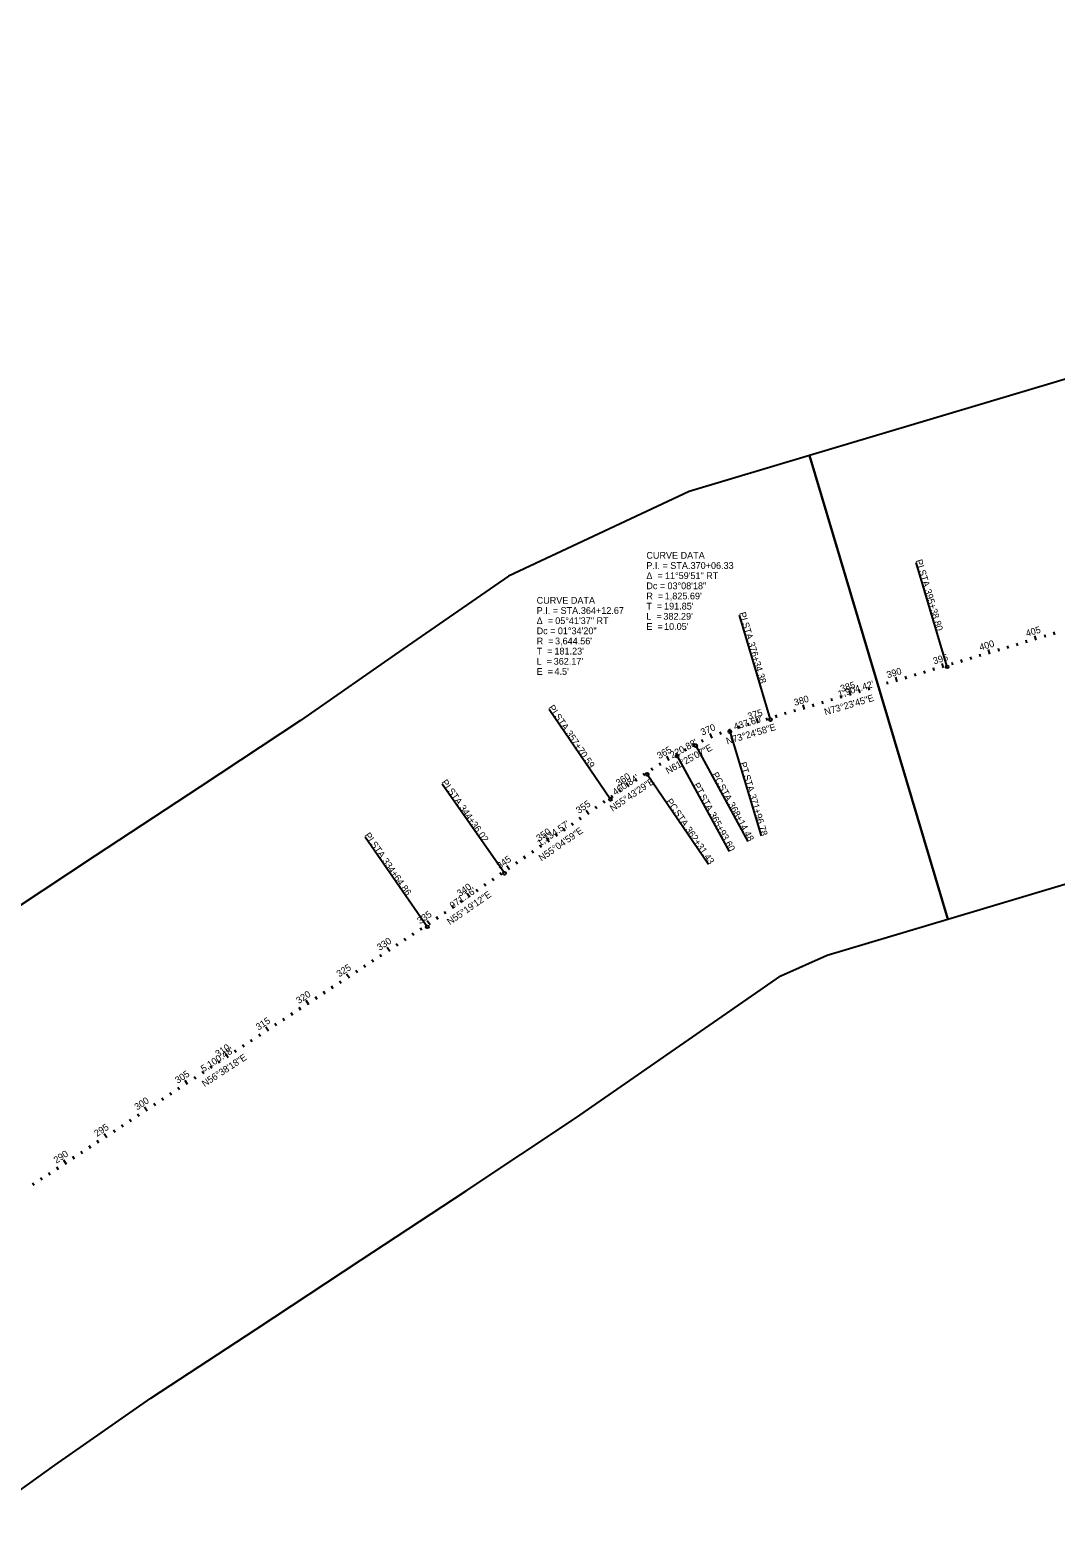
# Model space of a CAD drawing. Extents: x 187058 to 230449, y 263308 to 297406.
# Drawn here: x 208999 to 219600, y 281824 to 297406 of the extents above; entities that cross this region are included whole.
import ezdxf

# ---------------------------------------------------------------- set-up
doc = ezdxf.new("R2010")
doc.units = 0
for name, color, linetype in [('BR_X_Gen_Approach_Slab', 7, 'Continuous'), ('BR_X_SV_Deck_Top', 7, 'Continuous'), ('PV_X_Curb', 7, 'Continuous'), ('PV_X_Walk', 7, 'Continuous'), ('RD_X_GR_Lt', 7, 'Continuous'), ('SH_Named_Boundary', 7, 'Continuous')]:
    doc.layers.add(name, color=color, linetype=linetype)

msp = doc.modelspace()

# ---------------------------------------------------------------- linework, layer by layer
at = {"layer": 'BR_X_SV_Deck_Top'}
for p, q in [((219206, 291043), (219198, 291072)), ((219302, 291071), (219294, 291100)), ((219398, 291100), (219384, 291148)), ((219494, 291128), (219485, 291157)), ((219590, 291157), (219581, 291186)), ((218727, 290900), (218719, 290929)), ((218823, 290929), (218815, 290957)), ((218919, 290957), (218905, 291005)), ((219015, 290986), (219006, 291014)), ((219111, 291014), (219102, 291043)), ((218152, 290729), (218144, 290757)), ((218248, 290757), (218239, 290786)), ((218344, 290786), (218335, 290815)), ((218440, 290814), (218425, 290862)), ((218536, 290843), (218527, 290872)), ((218631, 290872), (218623, 290900)), ((217673, 290586), (217664, 290615)), ((217769, 290614), (217760, 290643)), ((217865, 290643), (217856, 290672)), ((217961, 290672), (217946, 290719)), ((218056, 290700), (218048, 290729)), ((217194, 290443), (217185, 290472)), ((217290, 290472), (217281, 290500)), ((217386, 290500), (217377, 290529)), ((217481, 290529), (217467, 290577)), ((217577, 290557), (217569, 290586)), ((216523, 290243), (216509, 290291)), ((216619, 290272), (216610, 290300)), ((216715, 290300), (216706, 290329)), ((216811, 290329), (216802, 290357)), ((216906, 290357), (216898, 290386)), ((217002, 290386), (216988, 290434)), ((217098, 290414), (217090, 290443)), ((216047, 290090), (216028, 290136)), ((216141, 290126), (216130, 290155)), ((216236, 290157), (216227, 290186)), ((216331, 290186), (216323, 290215)), ((216427, 290214), (216419, 290243)), ((215780, 289955), (215765, 289981)), ((215867, 290003), (215853, 290029)), ((215956, 290049), (215943, 290076)), ((215519, 289807), (215503, 289833)), ((215605, 289858), (215580, 289902)), ((215692, 289907), (215677, 289934)), ((215269, 289641), (215252, 289666)), ((215351, 289698), (215334, 289723)), ((215434, 289754), (215418, 289779)), ((215103, 289529), (215087, 289554)), ((215186, 289585), (215158, 289626)), ((214857, 289358), (214839, 289383)), ((214939, 289416), (214921, 289440)), ((215021, 289472), (215004, 289497)), ((214611, 289187), (214593, 289211)), ((214693, 289244), (214675, 289268)), ((214775, 289301), (214746, 289342)), ((214365, 289015), (214336, 289056)), ((214447, 289072), (214429, 289097)), ((214529, 289129), (214511, 289154)), ((214201, 288900), (214183, 288925)), ((214283, 288958), (214265, 288982)), ((213955, 288729), (213926, 288770)), ((214037, 288786), (214019, 288810)), ((214119, 288843), (214101, 288868)), ((213708, 288558), (213691, 288582)), ((213790, 288615), (213773, 288639)), ((213873, 288672), (213855, 288696)), ((213544, 288444), (213515, 288485)), ((213626, 288501), (213609, 288526)), ((213297, 288273), (213280, 288298)), ((213379, 288330), (213362, 288355)), ((213461, 288387), (213444, 288412)), ((213049, 288104), (213033, 288129)), ((213132, 288159), (213104, 288201)), ((213215, 288216), (213198, 288241)), ((212799, 287939), (212782, 287964)), ((212882, 287994), (212866, 288019)), ((212966, 288049), (212949, 288074)), ((212548, 287774), (212532, 287799)), ((212632, 287829), (212615, 287854)), ((212715, 287884), (212688, 287926)), ((212298, 287609), (212270, 287651)), ((212381, 287664), (212365, 287689)), ((212465, 287719), (212448, 287744)), ((212131, 287499), (212114, 287524)), ((212214, 287554), (212198, 287579)), ((211880, 287334), (211853, 287376)), ((211964, 287389), (211947, 287414)), ((212047, 287444), (212031, 287469)), ((211629, 287169), (211613, 287194)), ((211713, 287224), (211696, 287249)), ((211797, 287279), (211780, 287304)), ((211379, 287004), (211362, 287029)), ((211462, 287059), (211435, 287101)), ((211546, 287114), (211529, 287139)), ((211128, 286839), (211112, 286864)), ((211212, 286894), (211195, 286919)), ((211295, 286949), (211279, 286974)), ((210961, 286729), (210945, 286754)), ((211045, 286784), (211017, 286826)), ((210627, 286509), (210600, 286551)), ((210711, 286564), (210694, 286589)), ((210794, 286619), (210778, 286644)), ((210878, 286674), (210861, 286699)), ((210460, 286399), (210444, 286424)), ((210544, 286454), (210527, 286479)), ((210210, 286234), (210182, 286276)), ((210293, 286289), (210277, 286314)), ((210377, 286344), (210360, 286369)), ((209959, 286069), (209943, 286094)), ((210043, 286124), (210026, 286149)), ((210126, 286179), (210110, 286204)), ((209708, 285904), (209692, 285929)), ((209792, 285959), (209765, 286001)), ((209876, 286014), (209859, 286039)), ((209541, 285794), (209525, 285819)), ((209625, 285849), (209608, 285874)), ((209291, 285629), (209274, 285654)), ((209374, 285684), (209347, 285726)), ((209458, 285739), (209441, 285764)), ((209040, 285464), (209024, 285489)), ((209124, 285519), (209107, 285544)), ((209207, 285574), (209191, 285599))]:
    msp.add_line(p, q, dxfattribs=at)
at = {"layer": 'PV_X_Walk'}
for p, q in [((218477, 290826), (218156, 291904)), ((216652, 290281), (216330, 291359)), ((214996, 289456), (214363, 290386)), ((216232, 290156), (216554, 289078)), ((215880, 290010), (216418, 289022)), ((215686, 289904), (216224, 288916)), ((215377, 289715), (216011, 288786)), ((213902, 288692), (213258, 289615)), ((213104, 288139), (212463, 289065))]:
    msp.add_line(p, q, dxfattribs=at)
for centre in [(218477, 290826), (216652, 290281), (216232, 290156), (215880, 290010), (215686, 289904), (215377, 289715), (214996, 289456), (213902, 288692), (213104, 288139)]:
    msp.add_circle(centre, 15, dxfattribs=at)
at = {"layer": 'SH_Named_Boundary'}
for points in [[(217055, 293010), (218483, 288219), (219728, 288590), (220974, 288961), (222245, 289342), (223041, 289446), (225522, 290507), (226211, 291141), (226377, 291297), (229737, 294082), (229946, 294273), (230449, 295471), (225839, 297406), (225336, 296207), (225310, 296106), (225171, 296027), (223099, 295119), (222384, 294404), (222347, 294389), (220767, 294119), (219547, 293753), (218301, 293382)], [(205292, 285888), (208205, 281824), (209255, 282575), (210248, 283266), (211334, 283981), (212420, 284696), (213505, 285411), (214637, 286160), (215714, 286908), (216759, 287632), (217237, 287847), (218483, 288219), (217055, 293010), (215810, 292639), (213943, 291764), (212852, 291008), (211792, 290272), (210756, 289587), (209670, 288872), (208584, 288157), (207498, 287442), (206357, 286649)]]:
    msp.add_lwpolyline(points, close=True, dxfattribs=at)

# ---------------------------------------------------------------- texts
at = {"layer": 'BR_X_Gen_Approach_Slab'}
for s, rotation, p in [("1,904.42'", 16.6042, (217360, 290509)), ("437.60'", 16.5839, (216282, 290172)), ("220.88'", 28.5815, (215636, 289878)), ("460.84'", 34.2751, (215048, 289493)), ("1,334.57'", 34.917, (214269, 288967)), ("971.16'", 34.68, (213365, 288322)), ("5,100.48'", 33.3617, (210791, 286635))]:
    msp.add_text(s, height=70, rotation=rotation, dxfattribs=at).set_placement(p)
at = {"layer": 'BR_X_SV_Deck_Top'}
for s, rotation, p in [('405', 16.5814, (219301, 291136)), ('400', 16.5814, (218821, 290993)), ('395', 16.6042, (218343, 290851)), ('390', 16.6042, (217863, 290708)), ('385', 16.6042, (217384, 290565)), ('380', 16.6042, (216904, 290422)), ('375', 16.5839, (216426, 290279)), ('370', 22.7593, (215946, 290115)), ('365', 30.053, (215502, 289871)), ('360', 34.2751, (215082, 289590)), ('355', 34.917, (214671, 289305)), ('350', 34.917, (214260, 289018)), ('345', 34.917, (213851, 288733)), ('340', 34.68, (213439, 288448)), ('335', 34.68, (213029, 288164)), ('330', 33.3617, (212611, 287890)), ('325', 33.3617, (212194, 287616)), ('320', 33.3617, (211776, 287340)), ('315', 33.3617, (211359, 287066)), ('310', 33.3617, (210941, 286790)), ('305', 33.3617, (210524, 286516)), ('300', 33.3617, (210105, 286240)), ('295', 33.3617, (209689, 285966)), ('290', 33.3617, (209270, 285690))]:
    msp.add_text(s, height=70, rotation=rotation, dxfattribs=at).set_placement(p)
at = {"layer": 'PV_X_Curb'}
for s, p in [('CURVE DATA', (215368, 291943)), ('P.I. = STA. ', (215368, 291838)), ('370+06.33', (215825, 291838)), ('Δ  = ', (215368, 291733)), ('Dc = ', (215368, 291628)), ('11°59\'51" RT', (215560, 291733)), ('03°08\'18"', (215586, 291628)), ('CURVE DATA', (214234, 291478)), ('R  = ', (215368, 291523)), ("1,825.69'", (215558, 291523)), ('P.I. = STA. ', (214234, 291373)), ('364+12.67', (214691, 291373)), ('T  = ', (215368, 291418)), ('L  = ', (215368, 291313)), ("382.29'", (215544, 291313)), ("191.85'", (215551, 291418)), ('Δ  = ', (214234, 291268)), ('Dc = ', (214234, 291163)), ('05°41\'37" RT', (214426, 291268)), ('01°34\'20"', (214453, 291163)), ('E  = ', (215368, 291208)), ("10.05'", (215551, 291208)), ('R  = ', (214234, 291058)), ("3,644.56'", (214424, 291058)), ('T  = ', (214234, 290953)), ('L  = ', (214234, 290848)), ("362.17'", (214410, 290848)), ("181.23'", (214418, 290953)), ('E  = ', (214234, 290743)), ("4.5'", (214418, 290743))]:
    msp.add_text(s, height=70, dxfattribs=at).set_placement(p)
at = {"layer": 'PV_X_Walk'}
for s, rotation, p in [('PI', 286.5814, (218150, 291925)), (' STA. ', 286.5814, (218175, 291844)), ('395+38.80', 286.5814, (218242, 291618)), ('PI', 286.6042, (216325, 291381)), (' STA. ', 286.6042, (216349, 291300)), ('376+34.38', 286.6042, (216417, 291073)), ('PI', 304.2751, (214352, 290404)), (' STA. ', 304.2751, (214399, 290334)), ('357+70.59', 304.2751, (214532, 290139)), ('PT', 286.5839, (216331, 289831)), ('PC', 298.5815, (216043, 289714)), (' STA. ', 286.5839, (216362, 289725)), ('PI', 304.917, (213247, 289632)), (' STA. ', 304.917, (213296, 289563)), ('PT', 298.5815, (215850, 289606)), (' STA. ', 298.5815, (216098, 289613)), ('371+96.78', 286.5839, (216430, 289499)), ('344+36.02', 304.917, (213431, 289369)), ('PC', 304.2751, (215569, 289435)), (' STA. ', 298.5815, (215902, 289509)), ('368+14.48', 298.5815, (216211, 289405)), (' STA. ', 304.2751, (215634, 289341)), ('365+93.60', 298.5815, (216016, 289302)), ('PI', 304.68, (212451, 289084)), ('362+31.43', 304.2751, (215767, 289145)), (' STA. ', 304.68, (212500, 289014)), ('334+64.86', 304.68, (212634, 288820))]:
    msp.add_text(s, height=70, rotation=rotation, dxfattribs=at).set_placement(p)
at = {"layer": 'RD_X_GR_Lt'}
for s, rotation, p in [('N73°23\'45"E', 16.6042, (217218, 290324)), ('N73°24\'58"E', 16.5839, (216204, 290023)), ('N61°25\'07"E', 28.5815, (215591, 289716)), ('N55°43\'29"E', 34.2751, (215020, 289327)), ('N55°04\'59"E', 34.917, (214285, 288813)), ('N55°19\'12"E', 34.68, (213337, 288155)), ('N56°38\'18"E', 33.3617, (210802, 286481))]:
    msp.add_text(s, height=70, rotation=rotation, dxfattribs=at).set_placement(p)

doc.saveas('drawing.dxf')
